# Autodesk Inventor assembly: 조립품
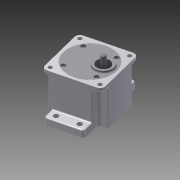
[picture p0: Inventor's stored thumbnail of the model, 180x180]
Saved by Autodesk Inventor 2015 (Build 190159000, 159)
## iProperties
Created: 2014-12
Part Number: 조립품
Document SubType Name: Assembly
Designer: bom
Author: bom
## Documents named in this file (11)
- C:\Users\bom\Desktop\메추라기\메추라기\Inventor2급\원본PDF\조립품.iam
- C:\Users\bom\Desktop\메추라기\메추라기\Inventor2급\본체.ipt
- C:\Users\bom\Desktop\메추라기\메추라기\Inventor2급\커버.ipt
- C:\Users\bom\Desktop\메추라기\메추라기\Inventor2급\오일실 8x22x7.ipt
- C:\Users\bom\Desktop\메추라기\메추라기\Inventor2급\베어링 608.ipt
- 베어링 608.ipt
- C:\Users\bom\Desktop\메추라기\메추라기\Inventor2급\메인축.ipt
- C:\Users\bom\Desktop\메추라기\메추라기\Inventor2급\서브축.ipt
- C:\Users\bom\Desktop\메추라기\메추라기\Inventor2급\오일실 17x32x8.ipt
- C:\Users\bom\Desktop\메추라기\메추라기\Inventor2급\베어링 6003.ipt
- 베어링 6003.ipt
